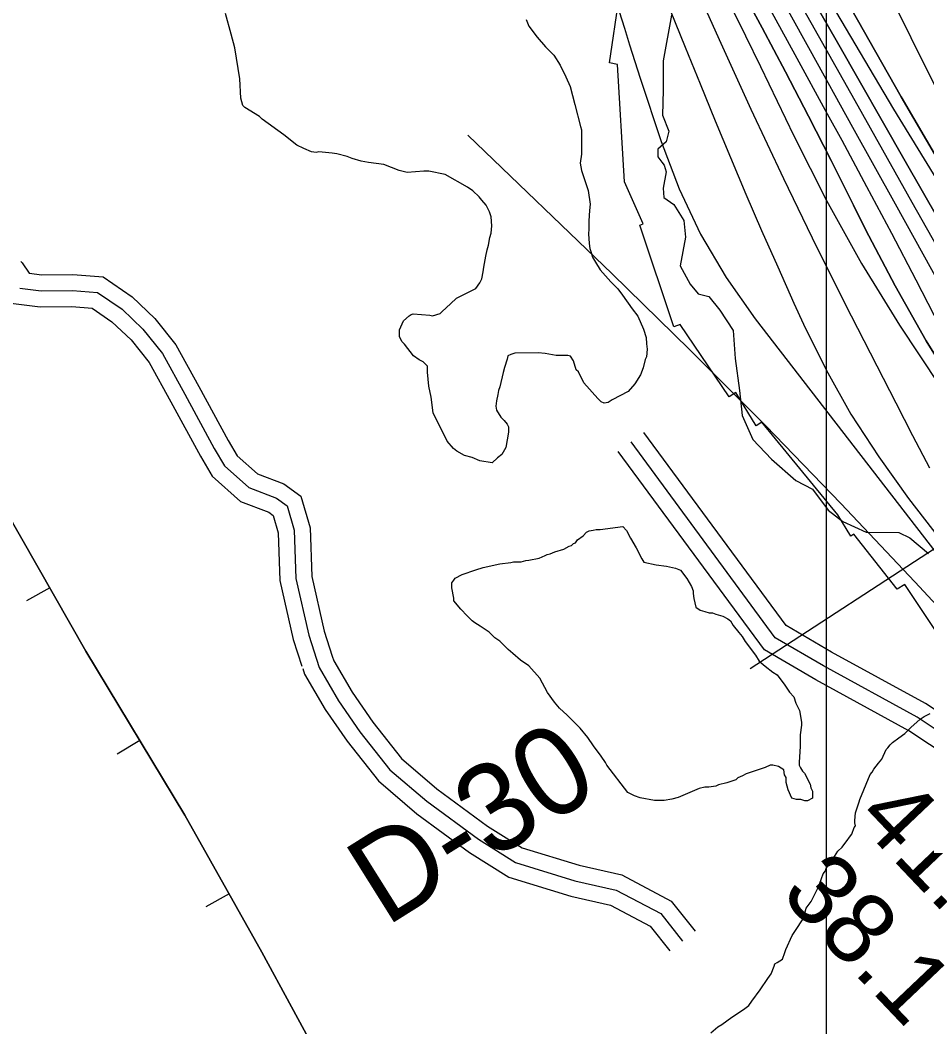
# Model space of a CAD drawing. Extents: x 3279314 to 3317160, y 734079 to 759431.
# Drawn here: x 3285321 to 3286173, y 753567 to 754513 of the extents above; entities that cross this region are included whole.
import ezdxf

# ---------------------------------------------------------------- set-up
doc = ezdxf.new("R2010")
doc.units = 0
for name, color, linetype in [('V-BORW-LINE', 7, 'Continuous'), ('V-GRID-MAJR', 7, 'Continuous'), ('V-RIVR-EDGE', 7, 'Continuous'), ('V-RIVR-RANG', 7, 'Continuous'), ('V-RIVR-RANG-IDEN', 7, 'Continuous'), ('V-ROAD-CNTR', 7, 'Continuous'), ('V-RRAP-RVMT', 7, 'Continuous'), ('V-SITE-VEGE', 7, 'Continuous'), ('V-TOPO-DPTH', 7, 'Continuous'), ('V-TOPO-MAJR', 7, 'Continuous'), ('V-TOPO-MINR', 7, 'Continuous'), ('V-TOPO-WATR', 7, 'Continuous')]:
    doc.layers.add(name, color=color, linetype=linetype)

msp = doc.modelspace()

# ---------------------------------------------------------------- linework, layer by layer
at = {"layer": 'V-BORW-LINE'}
for p, q in [((3285348.95, 753979.44), (3285327.24, 753967.04)), ((3285433.55, 753835.94), (3285412.14, 753823.03)), ((3285517.34, 753691.96), (3285495.55, 753679.7))]:
    msp.add_line(p, q, dxfattribs=at)
for points in [[(3284907.45, 754719.18), (3285075.75, 754436.63), (3285261.17, 754133.11), (3285382.92, 753919.96), (3285475.73, 753765.93), (3285548.16, 753637.18), (3285603.94, 753534.31), (3285703.22, 753356.01), (3285742.19, 753301.86), (3285868.32, 753195.58), (3285937.56, 753218.82), (3286033.9, 753289.55), (3286096.88, 753320.94), (3286216.73, 753294.15), (3286319.38, 753095.09), (3286388.32, 753019.82), (3286551.6, 752940.77), (3286688.04, 752908.66), (3286814.2, 752885.66), (3286896.94, 752894.8), (3286931.94, 752824.8), (3286914.44, 752765.74), (3286739.41, 752804.04)], [(3286739.41, 752804.04), (3286929.75, 752767.93), (3286934.12, 752831.36), (3286901.31, 752894.8), (3286814.2, 752885.66), (3286688.04, 752908.66), (3286551.6, 752940.77), (3286388.32, 753019.82), (3286319.38, 753095.09), (3286216.73, 753294.15), (3286096.88, 753320.94), (3286033.9, 753289.55), (3285937.56, 753218.82), (3285868.32, 753195.58), (3285742.19, 753301.86), (3285703.22, 753356.01), (3285603.94, 753534.31), (3285548.16, 753637.18), (3285475.73, 753765.93), (3285382.92, 753919.96), (3285261.17, 754133.11), (3285075.75, 754436.63), (3284907.45, 754719.18)]]:
    msp.add_lwpolyline(points, dxfattribs=at)
at = {"layer": 'V-GRID-MAJR'}
msp.add_spline([(3286080.65, 739457.23), (3286079.77, 745517.97), (3286078.89, 751579.8), (3286078.01, 757641.66), (3286078.01, 757642.71)], degree=3, dxfattribs=at)
at = {"layer": 'V-RIVR-EDGE'}
msp.add_lwpolyline([(3285932.92, 754517.3), (3285924.99, 754474.29), (3285924.92, 754446.91), (3285924.43, 754423.44), (3285930.48, 754408.21), (3285927.85, 754398.22), (3285920, 754391.28), (3285919.99, 754384.33), (3285923.89, 754379.1), (3285926.05, 754376.49), (3285927.78, 754369.96), (3285925.13, 754354.75), (3285925.54, 754346.06), (3285935.09, 754339.52), (3285944.61, 754324.28), (3285945.88, 754308.63), (3285941.03, 754281.69), (3285950.55, 754264.71), (3285957.92, 754255.57), (3285967.91, 754252.93), (3285978.31, 754240.3), (3285990.87, 754221.15), (3285992.54, 754194.63), (3285996.82, 754164.62), (3285999.37, 754141.14), (3286009.31, 754118.52), (3286026.65, 754100.22), (3286049.64, 754080.16), (3286065.27, 754071.87), (3286080, 754052.27), (3286093.88, 754041.8), (3286115.59, 754031.75), (3286146.45, 754031.24), (3286156.87, 754026.43), (3286174.22, 754011.61)], dxfattribs=at)
at = {"layer": 'V-RIVR-RANG'}
msp.add_line((3286006.78, 753903.69), (3286744.31, 754383.73), dxfattribs=at)
at = {"layer": 'V-ROAD-CNTR'}
for points in [[(3285321.74, 754285.95), (3285322.99, 754284.53), (3285329.51, 754274.83), (3285341.58, 754273.41), (3285370.73, 754273.73), (3285399.11, 754271.38), (3285426.31, 754252.71), (3285447.58, 754232.45), (3285467.24, 754207.68), (3285489.01, 754168.34), (3285516.5, 754117.63), (3285524.84, 754103.48), (3285543.92, 754086.47), (3285568.9, 754076.94), (3285584.78, 754065.6), (3285593.39, 754035.79), (3285594.96, 753990.08), (3285606.62, 753938.78), (3285614.24, 753915.24)], [(3285295.47, 754270.42), (3285295.57, 754270.25), (3285299.21, 754266.13), (3285312.31, 754246.66), (3285339.98, 754243.39), (3285369.66, 754243.72), (3285388.7, 754242.14), (3285407.36, 754229.34), (3285425.38, 754212.17), (3285442.19, 754190.97), (3285462.7, 754153.92), (3285490.38, 754102.87), (3285501.37, 754084.2), (3285528.08, 754060.41), (3285554.6, 754050.29), (3285558.86, 754047.25), (3285563.54, 754031.04), (3285565.08, 753986.21), (3285577.67, 753930.82), (3285585.76, 753905.81)], [(3285320.91, 754260.75), (3285340.78, 754258.4), (3285370.19, 754258.72), (3285393.91, 754256.76), (3285416.84, 754241.02), (3285436.48, 754222.31), (3285454.71, 754199.32), (3285475.86, 754161.13), (3285503.44, 754110.25), (3285513.1, 754093.84), (3285536, 754073.44), (3285561.75, 754063.61), (3285571.82, 754056.42), (3285578.47, 754033.41), (3285580.02, 753988.15), (3285592.14, 753934.8), (3285601.93, 753904.54), (3285620.18, 753873.15), (3285640.25, 753844.23), (3285668.45, 753808.48), (3285703.09, 753778.92), (3285751.63, 753743.12), (3285786.28, 753721.4), (3285842.22, 753704.2), (3285880.99, 753695.49), (3285922.82, 753673.38), (3285943.21, 753647.54)], [(3285320.91, 754260.75), (3285340.78, 754258.4), (3285370.19, 754258.72), (3285393.91, 754256.76), (3285416.84, 754241.02), (3285436.48, 754222.31), (3285454.71, 754199.32), (3285475.86, 754161.13), (3285503.44, 754110.25), (3285513.1, 754093.84), (3285536, 754073.44), (3285561.75, 754063.61), (3285571.82, 754056.42), (3285578.47, 754033.41), (3285580.02, 753988.15), (3285592.14, 753934.8), (3285601.93, 753904.54), (3285620.18, 753873.15), (3285640.25, 753844.23), (3285668.45, 753808.48), (3285703.09, 753778.92), (3285751.63, 753743.12), (3285786.28, 753721.4), (3285842.22, 753704.2), (3285880.99, 753695.49), (3285922.82, 753673.38), (3285943.21, 753647.54)], [(3286211.64, 753844), (3286171.31, 753870.84), (3286083.13, 753919.06), (3286040.57, 753943.89), (3285907, 754125.23)], [(3286203.05, 753831.7), (3286163.55, 753857.99), (3286075.75, 753906), (3286030.33, 753932.5), (3285894.92, 754116.33)], [(3286203.05, 753831.7), (3286163.55, 753857.99), (3286075.75, 753906), (3286030.33, 753932.5), (3285894.92, 754116.33)], [(3286194.46, 753819.4), (3286155.78, 753845.14), (3286068.38, 753892.94), (3286020.1, 753921.11), (3285882.85, 754107.43)], [(3285614.24, 753915.24), (3285615.71, 753910.68), (3285632.85, 753881.21), (3285652.31, 753853.16), (3285679.31, 753818.93), (3285712.42, 753790.68), (3285760.08, 753755.53), (3285792.58, 753735.16), (3285846.08, 753718.71), (3285886.23, 753709.69), (3285932.63, 753685.17), (3285954.99, 753656.83)], [(3285586.48, 753903.57), (3285588.16, 753898.39), (3285607.51, 753865.09), (3285628.19, 753835.3), (3285657.59, 753798.03), (3285693.76, 753767.16), (3285743.18, 753730.71), (3285779.99, 753707.64), (3285838.37, 753689.69), (3285875.75, 753681.29), (3285913, 753661.6), (3285931.44, 753638.25)]]:
    msp.add_lwpolyline(points, dxfattribs=at)
at = {"layer": 'V-RRAP-RVMT'}
for p, q in [((3285874.6, 754472.45), (3285902.92, 754664.29)), ((3285882.14, 754470.96), (3285874.6, 754472.45)), ((3285888.82, 754360.64), (3285882.14, 754470.96)), ((3285906.2, 754321.37), (3285888.82, 754360.64)), ((3285903.07, 754319.97), (3285906.2, 754321.37)), ((3285935.09, 754224.45), (3285903.07, 754319.97)), ((3285940.96, 754226.59), (3285935.09, 754224.45)), ((3285987.12, 754158.9), (3285940.96, 754226.59)), ((3285993.27, 754162.9), (3285987.12, 754158.9)), ((3286012.29, 754131.55), (3285993.27, 754162.9)), ((3286017.81, 754134.87), (3286012.29, 754131.55)), ((3286089.26, 754047.9), (3286017.81, 754134.87)), ((3286101.16, 754027.85), (3286089.26, 754047.9)), ((3286104.02, 754029.6), (3286101.16, 754027.85)), ((3286144.95, 753978.07), (3286104.02, 754029.6)), ((3286152.05, 753982.5), (3286144.95, 753978.07)), ((3286192.22, 753922.32), (3286152.05, 753982.5))]:
    msp.add_line(p, q, dxfattribs=at)
at = {"layer": 'V-SITE-VEGE'}
for points in [[(3285756.02, 754276.08), (3285756.63, 754280.61), (3285758.49, 754290.98), (3285759.74, 754296.82), (3285761.01, 754301.36), (3285762.25, 754308.49), (3285763.51, 754312.38), (3285764.1, 754319.51), (3285763.4, 754327.91), (3285762.06, 754332.44), (3285758.78, 754338.88), (3285754.87, 754343.38), (3285752.25, 754346.6), (3285746.38, 754352.38), (3285741.18, 754355.58), (3285720.38, 754367.72), (3285704.82, 754370.84), (3285700.29, 754370.81), (3285684.76, 754369.4), (3285676.98, 754371.28), (3285662.7, 754377), (3285648.44, 754378.83), (3285641.31, 754380.08), (3285632.88, 754382.6), (3285628.34, 754384.51), (3285618.61, 754387.03), (3285614.07, 754387.64), (3285601.77, 754388.84), (3285599.18, 754388.18), (3285594.65, 754388.79), (3285587.5, 754391.97), (3285581.01, 754395.16), (3285568.64, 754404.78), (3285548.46, 754419.51), (3285545.85, 754422.08), (3285532.2, 754430.4), (3285530.24, 754432.32), (3285528.25, 754439.43), (3285527.46, 754457.55), (3285522.71, 754486.64), (3285519.38, 754499.56), (3285514.06, 754518.94)], [(3285796.31, 754513.28), (3285798.95, 754506.83), (3285806.79, 754496.53), (3285814.63, 754487.53), (3285822.46, 754479.82), (3285828.35, 754470.15), (3285833.61, 754459.19), (3285837.56, 754450.16), (3285842.22, 754433.36)], [(3285842.22, 754433.36), (3285847.55, 754412.69), (3285848.23, 754409.46), (3285848.4, 754386.81), (3285847.16, 754378.38), (3285848.51, 754371.27), (3285850.5, 754364.82), (3285854.48, 754352.55), (3285856.51, 754339.62), (3285855.91, 754333.79), (3285855.33, 754324.07), (3285855.4, 754316.3), (3285854.78, 754311.77), (3285855.5, 754302.71), (3285856.18, 754298.19), (3285857.5, 754294.31), (3285858.83, 754289.79), (3285861.45, 754285.28), (3285866.04, 754278.19), (3285875.83, 754266.62), (3285882.35, 754260.19), (3285886.93, 754254.4), (3285896.08, 754241.53), (3285901.31, 754234.45), (3285906.59, 754222.19), (3285909.23, 754214.44), (3285909.28, 754208.61), (3285909.96, 754203.44), (3285909.37, 754196.32), (3285908.09, 754193.72), (3285906.21, 754185.93), (3285903.67, 754179.44), (3285898.55, 754170.99), (3285892.14, 754163.82), (3285877.3, 754155.94), (3285873.44, 754153.33), (3285869.56, 754152.65), (3285866.97, 754153.93), (3285863.71, 754157.14), (3285850.65, 754171.92), (3285845.39, 754182.24), (3285843.44, 754184.17), (3285840.79, 754192.57), (3285838.16, 754197.08), (3285835.57, 754197.7), (3285824.57, 754197.62), (3285814.2, 754199.49), (3285807.72, 754200.09), (3285785.71, 754199.92), (3285781.84, 754198.6), (3285779.26, 754197.28), (3285778.64, 754194.04), (3285776.1, 754186.26), (3285774.85, 754181.71), (3285771.71, 754168.1), (3285770.44, 754164.85), (3285769.82, 754160.96), (3285768.57, 754155.13), (3285767.96, 754149.95), (3285768.64, 754146.07), (3285772.57, 754139.62), (3285775.83, 754136.41), (3285778.44, 754133.2), (3285779.76, 754130.62), (3285779.8, 754125.44), (3285777.31, 754111.18), (3285773.48, 754104.68), (3285769.62, 754101.41), (3285764.48, 754096.84), (3285752.81, 754098.7), (3285745.67, 754101.88), (3285738.53, 754103.77), (3285731.38, 754107.6), (3285728.13, 754110.16), (3285722.25, 754117.24), (3285709.11, 754143.68), (3285707.05, 754158.55), (3285705.04, 754168.9), (3285703.64, 754181.83), (3285703.6, 754187.65), (3285699.69, 754191.51), (3285695.79, 754193.42), (3285690.58, 754197.27), (3285682.09, 754208.21), (3285679.48, 754210.78), (3285677.5, 754215.29), (3285677.45, 754221.77), (3285681.27, 754230.21), (3285686.42, 754234.78), (3285688.35, 754236.08), (3285690.29, 754236.75), (3285705.83, 754235.57), (3285708.42, 754234.94), (3285715.53, 754236.94), (3285717.46, 754238.89), (3285725.17, 754246.07), (3285730.96, 754251.29), (3285749.01, 754260.49), (3285752.86, 754265.7), (3285754.77, 754269.59), (3285756.02, 754276.08)], [(3285977.11, 753794.21), (3285974.53, 753792.9), (3285968.06, 753792.21), (3285964.18, 753792.18), (3285959.01, 753790.84), (3285948.04, 753786.23), (3285939.01, 753782.28), (3285933.19, 753780.94), (3285926.08, 753779.59), (3285917.02, 753779.53), (3285903.41, 753782.01), (3285898.22, 753783.92), (3285891.72, 753787.1), (3285872.11, 753812.85), (3285870.8, 753815.43), (3285866.87, 753821.22), (3285859.68, 753830.88), (3285854.44, 753838.61), (3285847.25, 753847.61), (3285834.86, 753859.82), (3285827.69, 753866.24), (3285823.12, 753872.03), (3285816.58, 753881.04), (3285809.36, 753894.58), (3285798.92, 753906.16), (3285791.11, 753911.28), (3285783.94, 753917.69), (3285779.38, 753921.54), (3285771.56, 753929.25), (3285767, 753932.45), (3285761.79, 753937.59), (3285753.33, 753943.36), (3285748.12, 753946.55), (3285745.52, 753948.48), (3285740.96, 753952.97), (3285735.08, 753959.4), (3285728.55, 753967.12), (3285728.53, 753969.71), (3285726.52, 753979.41), (3285726.49, 753983.93), (3285728.41, 753986.54), (3285729.69, 753988.49), (3285736.13, 753991.77), (3285749.05, 753996.4), (3285756.15, 753998.4), (3285771.66, 754001.75), (3285782.01, 754003.12), (3285784.59, 754003.79), (3285791.71, 754003.84), (3285796.23, 754005.17), (3285798.82, 754005.19), (3285808.51, 754007.2), (3285814.32, 754009.83), (3285816.26, 754010.5), (3285818.84, 754011.16), (3285823.36, 754013.14), (3285831.75, 754015.79), (3285836.91, 754018.42), (3285838.85, 754019.08), (3285840.77, 754021.04), (3285842.71, 754021.7), (3285844.64, 754024.3), (3285849.78, 754028.22), (3285853, 754031.48), (3285855.58, 754032.8), (3285859.45, 754033.47), (3285862.04, 754034.14), (3285865.92, 754034.17), (3285887.26, 754036.92), (3285890.53, 754033.06), (3285894.46, 754025.97), (3285899.71, 754016.95), (3285904.96, 754006.63), (3285906.93, 754003.41), (3285918.6, 754000.91), (3285928.32, 753999.69), (3285936.75, 753997.81), (3285941.29, 753995.9), (3285947.17, 753988.18), (3285951.76, 753980.44), (3285953.09, 753976.57), (3285953.11, 753973.98), (3285953.79, 753969.45), (3285955.79, 753961.05), (3285959.7, 753958.49), (3285964.24, 753957.23), (3285968.13, 753955.97), (3285971.37, 753955.99), (3285974.61, 753954.72), (3285976.56, 753954.09), (3285981.1, 753952.83), (3285985.65, 753950.28), (3285988.25, 753948.35), (3285990.87, 753943.84), (3285996.1, 753937.41), (3285999.37, 753933.55), (3286001.99, 753929.04), (3286011.79, 753916.16), (3286015.07, 753910.36), (3286020.93, 753905.88), (3286028.1, 753900.1)], [(3286028.1, 753900.1), (3286032, 753897.55), (3286039.19, 753887.89), (3286043.77, 753881.45), (3286047.69, 753876.95), (3286049.67, 753871.14), (3286052.96, 753864.04), (3286054.99, 753853.05), (3286055, 753850.46), (3286053.78, 753841.39), (3286053.86, 753830.39), (3286052.68, 753815.5), (3286052.7, 753812.91), (3286054.01, 753810.33), (3286055.98, 753807.1), (3286057.93, 753805.18), (3286063.19, 753794.86), (3286063.86, 753791.63), (3286065.18, 753788.4), (3286065.23, 753781.93), (3286060.72, 753779.31), (3286058.13, 753779.29), (3286054.23, 753780.55), (3286050.35, 753780.52), (3286045.81, 753781.79), (3286042.52, 753789.53), (3286040.52, 753796.63), (3286040.49, 753801.16), (3286039.17, 753803.74), (3286038.49, 753808.27), (3286033.29, 753811.46), (3286028.1, 753812.72), (3286025.51, 753812.7), (3286021, 753810.73), (3286015.19, 753808.74), (3286002.92, 753804.77), (3285999.7, 753802.8), (3285995.18, 753800.82), (3285993.25, 753798.87), (3285984.86, 753796.21), (3285977.11, 753794.21)], [(3286059.51, 753678.47), (3286063.91, 753684.6), (3286070.5, 753697.95), (3286072.14, 753701.84), (3286075.42, 753710.74), (3286077.62, 753713.53), (3286078.17, 753715.75), (3286081.47, 753720.76), (3286085.88, 753726.89), (3286089.18, 753731.9), (3286093.04, 753735.81), (3286095.79, 753739.15), (3286098, 753741.94), (3286100.2, 753745.28), (3286102.4, 753748.07), (3286104.59, 753754.18), (3286105.69, 753755.85), (3286105.12, 753758.62), (3286105.11, 753760.84), (3286105.62, 753768.06), (3286106.38, 753769.98), (3286109.14, 753778.39), (3286109.69, 753780.61), (3286119.54, 753803.97), (3286121.2, 753806.2), (3286122.85, 753808.98), (3286127.25, 753814.55), (3286130.56, 753818.46), (3286134.4, 753827.36), (3286136.05, 753829.03), (3286138.26, 753831.82), (3286140.46, 753834.05), (3286146.54, 753838.52), (3286152.07, 753842.43), (3286157.59, 753848.02), (3286166.42, 753855.83), (3286170.29, 753858.63), (3286175.83, 753861.43)], [(3285969.71, 753561.45), (3285976.33, 753567.04), (3285980.21, 753569.28), (3285989.6, 753575.99), (3286000.66, 753583.27), (3286005.63, 753587.18), (3286008.39, 753591.07), (3286016.1, 753601.66), (3286023.25, 753612.24), (3286026.55, 753616.7), (3286029.29, 753623.93), (3286029.83, 753626.15), (3286032.04, 753627.27), (3286037.02, 753630.63), (3286039.21, 753636.74), (3286040.3, 753639.52), (3286046.33, 753652.87), (3286051.83, 753661.23), (3286056.79, 753669.02), (3286059.51, 753678.47)]]:
    msp.add_lwpolyline(points, dxfattribs=at)
at = {"layer": 'V-TOPO-DPTH'}
for points in [[(3286025.02, 754602.95), (3286088.7, 754491.53), (3286152.39, 754380.12), (3286216.1, 754268.72)], [(3286216.1, 754268.72), (3286152.39, 754380.12), (3286088.7, 754491.53), (3286025.02, 754602.95)], [(3286023.22, 754556.14), (3286063.1, 754484.11), (3286102.99, 754412.07), (3286142.87, 754340.03), (3286186.7, 754260.85)], [(3286023.22, 754556.14), (3286063.1, 754484.11), (3286102.99, 754412.07), (3286142.87, 754340.03), (3286186.7, 754260.85)], [(3286196.31, 754359.07), (3286148.63, 754440.57), (3286083.88, 754555.15)], [(3286196.31, 754359.07), (3286148.63, 754440.57), (3286083.88, 754555.15)], [(3286203.57, 754160.73), (3286172.05, 754211.2), (3286142.87, 754263.05), (3286115.24, 754315.83), (3286103.91, 754338.74), (3286082.93, 754380.66), (3286061.68, 754422.44), (3286040.03, 754464.02), (3286018.11, 754505.46), (3285995.94, 754546.77)], [(3286145.33, 754520.86), (3286169.77, 754471.69), (3286194.68, 754422.76)], [(3286145.33, 754520.86), (3286169.77, 754471.69), (3286194.68, 754422.76)]]:
    msp.add_lwpolyline(points, dxfattribs=at)
at = {"layer": 'V-TOPO-MAJR'}
msp.add_lwpolyline([(3285931.71, 754521.84), (3285945.68, 754487.21), (3285959.75, 754452.63), (3285973.95, 754418.1), (3285988.26, 754383.61), (3286002.79, 754349.22), (3286017.54, 754314.93), (3286032.6, 754280.77), (3286047.89, 754246.71), (3286056.8, 754227.08), (3286078.14, 754184.15), (3286101.38, 754142.36), (3286127.47, 754102.28), (3286155.46, 754063.36), (3286329.11, 753838.83)], dxfattribs=at)
at = {"layer": 'V-TOPO-MINR'}
for points in [[(3286025.02, 754602.95), (3286088.7, 754491.53), (3286152.39, 754380.12), (3286216.1, 754268.72)], [(3285934.22, 754591.53), (3285977.6, 754494.31), (3286007.43, 754428.86), (3286037.94, 754363.74), (3286069.48, 754299.11), (3286101.69, 754234.81), (3286143.51, 754152.96), (3286159.24, 754122.48), (3286175.12, 754092.08)], [(3286083.88, 754555.15), (3286148.63, 754440.57), (3286196.31, 754359.07)], [(3285995.94, 754546.77), (3286018.11, 754505.46), (3286040.03, 754464.02), (3286061.68, 754422.44), (3286082.93, 754380.66), (3286103.91, 754338.74), (3286115.24, 754315.83), (3286142.87, 754263.05), (3286172.05, 754211.2), (3286203.57, 754160.73)], [(3286018.39, 754536.08), (3286048.83, 754480.3), (3286079.24, 754424.51), (3286092.71, 754399.75), (3286116.18, 754356.23), (3286139.41, 754312.59), (3286162.29, 754268.77), (3286184.94, 754224.82)], [(3285988.34, 754526.48), (3286002.54, 754497.77), (3286016.52, 754468.95), (3286047.63, 754403.88), (3286078.47, 754343.3), (3286111.25, 754283.85), (3286146.94, 754226.11), (3286184.57, 754169.5)], [(3286082.99, 754528.02), (3286141.38, 754428.93), (3286201.63, 754331.03)], [(3285883.77, 754520.78), (3285888.61, 754505.1), (3285893.51, 754489.44), (3285898.5, 754473.81), (3285903.56, 754458.21), (3285923.13, 754398.48), (3285940.22, 754354.19), (3285960.15, 754311.41), (3285984.37, 754270.9), (3286011.44, 754231.9), (3286314.6, 753839.92)], [(3286057, 754522.6), (3286107.8, 754432.14), (3286158.64, 754341.7), (3286209.51, 754251.28)], [(3286145.33, 754520.86), (3286169.77, 754471.69), (3286194.68, 754422.76)], [(3285741.68, 754404.44), (3285877.27, 754274.15), (3285949.78, 754203.26), (3286021.47, 754131.56), (3286091.91, 754058.64), (3286161.52, 753984.9), (3286297.26, 753838.62)]]:
    msp.add_lwpolyline(points, dxfattribs=at)
at = {"layer": 'V-TOPO-WATR'}
msp.add_lwpolyline([(3286023.22, 754556.14), (3286063.1, 754484.11), (3286102.99, 754412.07), (3286142.87, 754340.03), (3286186.7, 754260.85)], dxfattribs=at)

# ---------------------------------------------------------------- texts
at = {"layer": 'V-RIVR-RANG'}
for s, p in [('41.2', (3286104.54, 753761.7)), ('38.1', (3286033.86, 753690.92))]:
    msp.add_text(s, height=67, rotation=313.53833, dxfattribs=at).set_placement(p)
at = {"layer": 'V-RIVR-RANG-IDEN'}
msp.add_text('D-30', height=83, rotation=32.08513, dxfattribs=at).set_placement((3285664.55, 753660.39))

doc.saveas('drawing.dxf')
